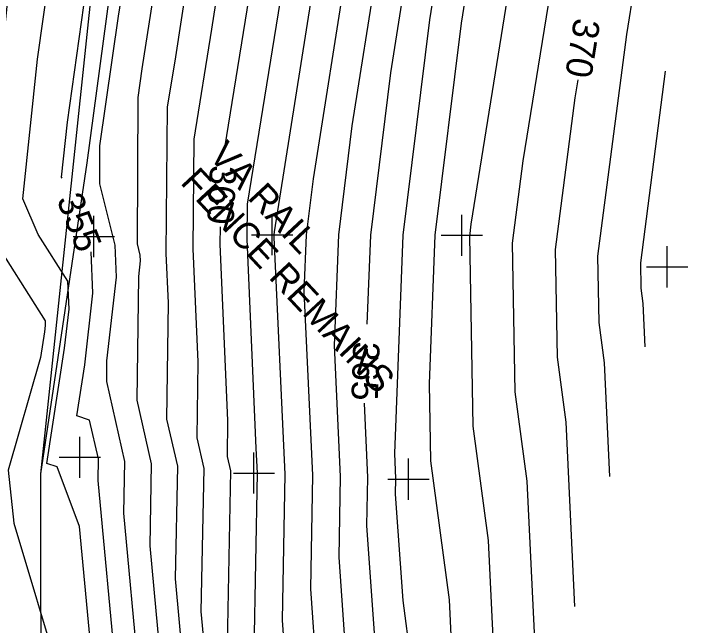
# Model space of a CAD drawing. Extents: x 487096 to 489566, y 221939 to 224454.
# Drawn here: x 488437.3 to 488522, y 222981.8 to 223055.9 of the extents above; entities that cross this region are included whole.
import ezdxf

# ---------------------------------------------------------------- set-up
doc = ezdxf.new("R2010")
doc.units = 0
for name, color, linetype in [('SV_FENC_FENCES', 7, 'Continuous'), ('SV_FENC_FENCES_TX', 7, 'Continuous'), ('SV_ROWL_HWYLOC', 7, 'Continuous'), ('SV_SURF_INDEX_CONTOUR', 7, 'Continuous'), ('SV_SURF_INTER_CONTOUR', 7, 'Continuous'), ('SV_SURF_SPOT', 7, 'Continuous')]:
    doc.layers.add(name, color=color, linetype=linetype)

msp = doc.modelspace()

# ---------------------------------------------------------------- linework, layer by layer
at = {"layer": 'SV_FENC_FENCES'}
msp.add_lwpolyline([(488453.433, 223114.138), (488451.207, 223076.067), (488446.069, 223037.804), (488440.473, 223000.117)], dxfattribs=at)
at = {"layer": 'SV_ROWL_HWYLOC'}
msp.add_lwpolyline([(488463.166, 223231.249), (488461.577, 223189.461), (488456.439, 223151.488), (488440.473, 223000.117), (488440.593, 222898.56), (488442.958, 222863.746), (488470.321, 222775.783)], dxfattribs=at)
at = {"layer": 'SV_SURF_INDEX_CONTOUR'}
for points in [[(488478.783, 223124.096), (488477.207, 223113.143), (488471.304, 223095.978), (488471.518, 223095.657), (488470.253, 223083.607), (488467.914, 223071.051), (488466.599, 223063.645), (488465.711, 223057.894), (488462.761, 223039.626)], [(488443.076, 223035.953), (488443.017, 223036.089), (488443.721, 223042.75), (488446.002, 223058.967), (488449.26, 223063.173), (488449.452, 223063.705), (488449.37, 223064.219), (488446.135, 223072.869), (488446.273, 223081.458), (488446.41, 223095.856), (488446.75, 223106.239), (488448.644, 223120.248)], [(488480.066, 223018.266), (488480.49, 223029.059), (488482.921, 223048.74), (488484.867, 223061.071), (488488.565, 223077.394), (488488.535, 223079.575), (488489.571, 223083.057), (488496.378, 223102.641)], [(488505.573, 223047.87), (488505.225, 223045.703), (488502.831, 223027.29), (488503.073, 223014.244), (488504.12, 223006.385), (488505.193, 222984.021)], [(488462.235, 223030.041), (488462.217, 223027.97), (488463.149, 223006.553), (488463.095, 223002.219), (488463.496, 223000.46), (488463.083, 222979.446), (488463.324, 222976.857), (488464.375, 222973.809), (488472.432, 222950.186), (488474.437, 222945.672)], [(488460.87, 222944.221), (488458.849, 222947.603), (488457.938, 222950.15), (488456.322, 222956.204), (488449.658, 222975.519), (488447.446, 222999.309), (488447.497, 223001.903), (488446.422, 223006.622), (488444.869, 223007.133), (488445.818, 223013.333), (488446.796, 223022.007), (488446.605, 223027.025)], [(488495.711, 222924.435), (488495.563, 222925.12), (488491.398, 222939.244), (488487.15, 222949.704), (488482.925, 222970.039), (488481.314, 222975.692), (488480.037, 222993.827), (488480.141, 222999.659), (488479.725, 223008.672)]]:
    msp.add_lwpolyline(points, dxfattribs=at)
at = {"layer": 'SV_SURF_INTER_CONTOUR'}
for points in [[(488460.59, 222976.589), (488459.956, 222983.419), (488460.296, 223000.749), (488459.444, 223004.485), (488459.559, 223013.692), (488458.963, 223027.389), (488459.082, 223040.668), (488461.239, 223054.025), (488462.885, 223064.685), (488465.323, 223078.414), (488466.334, 223083.841), (488467.884, 223098.601), (488467.745, 223098.809), (488471.57, 223109.933), (488474.236, 223128.456), (488484.779, 223151.794), (488487.024, 223159.98), (488485.958, 223166.521), (488488.263, 223186.974), (488486.666, 223195.898), (488481.852, 223212.777), (488477.1, 223228.476)], [(488490.866, 223226.171), (488492.012, 223217.495), (488497.642, 223186.03), (488496.447, 223175.425), (488499.417, 223157.205), (488493.162, 223134.401), (488489.425, 223126.129), (488488.48, 223119.564), (488478.423, 223090.314), (488478.788, 223089.767), (488478.092, 223083.138), (488475.182, 223067.522), (488473.962, 223062.133), (488468.804, 223029.451), (488468.76, 223029.098), (488468.746, 223028.74), (488470.07, 223000.056), (488469.755, 222982.34), (488470.159, 222976.6)], [(488494.436, 223225.954), (488496.881, 223207.44), (488500.768, 223185.715), (488499.943, 223178.393), (488503.548, 223156.28), (488495.957, 223128.604), (488494.488, 223125.354), (488494.117, 223122.774), (488481.982, 223087.482), (488482.422, 223086.822), (488482.011, 223082.903), (488480.291, 223073.671), (488477.597, 223061.779), (488473.509, 223035.881), (488472.67, 223029.085), (488472.399, 223022.193), (488473.427, 222999.924), (488473.182, 222986.169), (488473.877, 222976.297)], [(488498.006, 223225.737), (488501.75, 223197.385), (488503.894, 223185.401), (488503.439, 223181.362), (488506.352, 223163.498), (488507.163, 223152.923), (488499.358, 223124.575), (488498.634, 223122.6), (488494.54, 223110.822), (488485.541, 223084.65), (488486.057, 223083.878), (488485.93, 223082.668), (488485.399, 223079.82), (488481.232, 223061.425), (488478.215, 223042.311), (488476.58, 223029.072), (488476.052, 223015.647), (488476.784, 222999.791), (488476.61, 222989.998), (488477.596, 222975.994)], [(488487.658, 223224.665), (488494.515, 223186.345), (488492.951, 223172.457), (488495.286, 223158.13), (488490.368, 223140.199), (488484.362, 223126.905), (488482.843, 223116.354), (488474.864, 223093.146), (488475.153, 223092.712), (488474.173, 223083.372), (488470.505, 223063.688), (488470.313, 223062.604), (488470.183, 223061.763), (488465.509, 223032.811), (488465.47, 223028.55), (488466.572, 223003.231), (488466.713, 223000.189), (488466.327, 222978.511)], [(488510.643, 223171.963), (488513.088, 223140.074), (488508.388, 223123.002), (488503.56, 223109.836), (488494.746, 223084.477), (488490.153, 223069.041), (488490.166, 223068.06), (488488.503, 223060.717), (488487.627, 223055.17), (488484.401, 223029.047), (488483.358, 223002.554), (488483.498, 222999.527), (488483.465, 222997.657), (488484.374, 222984.742), (488485.324, 222977.615), (488485.606, 222971.742), (488490.22, 222949.533), (488492.945, 222942.823), (488498.078, 222925.416), (488502.361, 222905.595)], [(488501.004, 222923.807), (488500.592, 222925.712), (488494.491, 222946.402), (488493.289, 222949.363), (488491.254, 222959.16), (488490.023, 222984.808), (488487.775, 223001.676), (488487.602, 223011.014), (488488.311, 223029.034), (488491.485, 223054.733), (488492.39, 223060.375), (488492.981, 223062.576), (488499.92, 223085.897), (488506.022, 223103.454), (488512.903, 223122.216), (488516.051, 223133.65), (488514.413, 223155.007)], [(488457.857, 222976.322), (488456.828, 222987.391), (488457.096, 223001.037), (488455.794, 223006.751), (488455.97, 223020.832), (488455.71, 223026.809), (488455.869, 223044.596), (488456.767, 223050.157), (488459.17, 223065.725), (488461.699, 223079.96), (488461.97, 223083.115), (488461.843, 223084.332), (488462.873, 223088.441), (488464.249, 223101.546), (488464.186, 223101.641), (488465.933, 223106.723), (488467.291, 223116.157), (488466.273, 223123.357), (488467.097, 223134.596), (488477.188, 223146.975)], [(488452.391, 222975.787), (488450.574, 222995.337), (488450.697, 223001.615), (488448.493, 223011.284), (488448.524, 223013.807), (488449.669, 223023.963), (488449.521, 223027.831), (488447.653, 223035.26), (488447.676, 223039.857), (488449.916, 223055.592), (488450.509, 223059.436), (488452.522, 223064.989), (488450.982, 223074.611), (488450.584, 223075.674), (488450.601, 223076.73), (488450.697, 223086.782), (488450.875, 223095.746), (488451.336, 223097.566), (488450.912, 223100.567), (488451.272, 223111.584), (488451.891, 223116.159), (488456.501, 223137.591), (488458.737, 223146.727)], [(488446.925, 222975.252), (488445.206, 222993.736), (488442.482, 223000.955), (488441.252, 223001.36), (488443.39, 223015.327), (488443.922, 223020.052), (488443.793, 223023.448), (488440.199, 223029.118), (488438.317, 223033.448), (488440.107, 223050.364), (488441.599, 223060.97), (488443.951, 223064.007), (488441.686, 223070.063), (488441.944, 223086.185), (488442.026, 223094.731), (488442.227, 223100.893), (488445.435, 223124.619), (488447.825, 223135.727), (488450.162, 223145.275)], [(488444.738, 223139.906), (488443.486, 223134.795), (488442.207, 223128.85), (488437.705, 223095.548), (488437.641, 223093.606), (488437.615, 223090.913), (488437.236, 223067.257), (488438.303, 223064.405), (488437.196, 223062.974), (488436.493, 223057.978), (488433.618, 223030.808), (488434.258, 223029.334), (488441.028, 223018.654), (488441.049, 223018.096), (488440.962, 223017.32), (488440.482, 223014.189), (488436.564, 223000.533), (488437.239, 222994.108), (488442.853, 222975.364)], [(488460.839, 223138.522), (488458.646, 223128.326), (488457.838, 223117.301), (488459.381, 223106.384), (488459.84, 223103.137), (488455.872, 223087.468), (488455.786, 223083.138), (488456.183, 223079.326), (488455.248, 223068.425), (488455.593, 223066.274), (488455.241, 223065.305), (488452.761, 223049.224), (488452.262, 223045.717), (488452.171, 223027.998), (488452.515, 223026.631), (488452.542, 223025.918), (488452.331, 223024.048), (488452.143, 223009.018), (488453.897, 223001.326), (488453.701, 222991.364), (488455.124, 222976.054)], [(488518.184, 223138.051), (488519.014, 223127.225), (488517.418, 223121.43), (488508.485, 223097.072), (488505.095, 223087.317), (488501.239, 223074.359), (488497.407, 223060.088), (488492.642, 223030.377), (488492.447, 223028.883), (488492.874, 223005.865), (488494.722, 222992), (488496.615, 222952.542)], [(488521.954, 223121.094), (488521.977, 223120.801), (488521.933, 223120.644), (488510.948, 223090.69), (488510.269, 223088.737), (488509.497, 223086.142), (488502.423, 223059.801), (488498.933, 223038.04), (488497.639, 223028.086), (488497.973, 223010.055), (488499.421, 222999.193), (488500.904, 222968.281)], [(488509.482, 222999.76), (488508.819, 223013.578), (488508.172, 223018.433), (488508.022, 223026.494), (488511.517, 223053.366), (488512.457, 223059.227), (488514.794, 223067.931), (488517.761, 223075.778)], [(488513.771, 223015.5), (488513.518, 223020.771), (488513.271, 223022.623), (488513.214, 223025.697), (488516.233, 223048.913)]]:
    msp.add_lwpolyline(points, dxfattribs=at)
at = {"layer": 'SV_SURF_SPOT'}
for p, q in [((488468.546, 223026.598), (488468.546, 223031.6)), ((488491.53, 223026.522), (488491.53, 223031.524)), ((488446.923, 223026.373), (488446.923, 223031.375)), ((488466.045, 223029.099), (488471.047, 223029.099)), ((488468.546, 223029.099), (488468.546, 223029.099)), ((488489.029, 223029.023), (488494.031, 223029.023)), ((488491.53, 223029.023), (488491.53, 223029.023)), ((488444.422, 223028.874), (488449.424, 223028.874)), ((488446.923, 223028.874), (488446.923, 223028.874)), ((488516.416, 223022.705), (488516.416, 223027.707)), ((488513.915, 223025.206), (488518.917, 223025.206)), ((488516.416, 223025.206), (488516.416, 223025.206)), ((488445.245, 222999.605), (488445.245, 223004.607)), ((488442.744, 223002.106), (488447.746, 223002.106)), ((488445.245, 223002.106), (488445.245, 223002.106)), ((488466.341, 222997.702), (488466.341, 223002.704)), ((488485.082, 222996.963), (488485.082, 223001.965)), ((488463.84, 223000.203), (488468.842, 223000.203)), ((488466.341, 223000.203), (488466.341, 223000.203)), ((488482.581, 222999.464), (488487.583, 222999.464)), ((488485.082, 222999.464), (488485.082, 222999.464))]:
    msp.add_line(p, q, dxfattribs=at)

# ---------------------------------------------------------------- texts
at = {"layer": 'SV_FENC_FENCES_TX'}
for s, p in [('VA RAIL', (488460.743, 223038.55)), ('FENCE REMAINS', (488457.308, 223035.342))]:
    msp.add_text(s, height=3.2, rotation=313.03859, dxfattribs=at).set_placement(p)
at = {"layer": 'SV_SURF_INDEX_CONTOUR'}
for s, rotation, p in [('370', 260.88883, (488505.173, 223055.481)), ('360', 266.86269, (488461.045, 223037.568)), ('355', 291.60717, (488442.38, 223033.366)), ('365', 267.96461, (488478.39, 223016.176))]:
    msp.add_text(s, height=3.2, rotation=rotation, dxfattribs=at).set_placement(p)

doc.saveas('drawing.dxf')
